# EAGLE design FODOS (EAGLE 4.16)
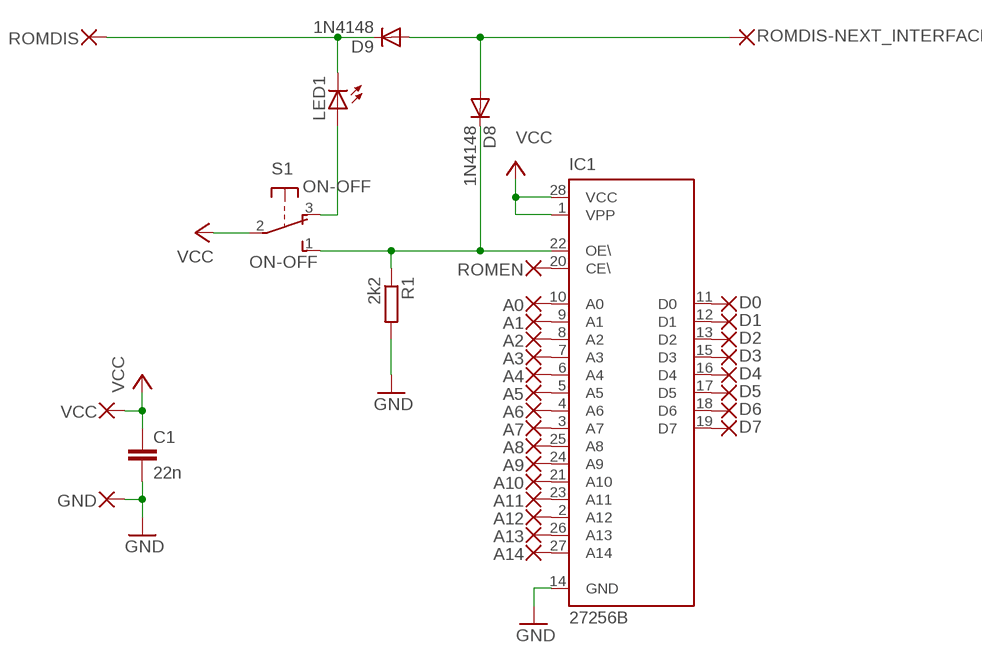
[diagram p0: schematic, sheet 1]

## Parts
A0  1,27-REDONDO1.0  [1,27/1,0-REDONDO]
A1  1,27-REDONDO1.0  [1,27/1,0-REDONDO]
A2  1,27-REDONDO1.0  [1,27/1,0-REDONDO]
A3  1,27-REDONDO1.0  [1,27/1,0-REDONDO]
A4  1,27-REDONDO1.0  [1,27/1,0-REDONDO]
A5  1,27-REDONDO1.0  [1,27/1,0-REDONDO]
A6  1,27-REDONDO1.0  [1,27/1,0-REDONDO]
A7  1,27-REDONDO1.0  [1,27/1,0-REDONDO]
A8  1,27-REDONDO1.0  [1,27/1,0-REDONDO]
A9  1,27-REDONDO1.0  [1,27/1,0-REDONDO]
A10  1,27-REDONDO1.0  [1,27/1,0-REDONDO]
A11  1,27-REDONDO1.0  [1,27/1,0-REDONDO]
A12  1,27-REDONDO1.0  [1,27/1,0-REDONDO]
A13  1,27-REDONDO1.0  [1,27/1,0-REDONDO]
A14  1,27-REDONDO1.0  [1,27/1,0-REDONDO]
C1  22n  C-EU050-024X044  [C050-024X044]
D0  1,27-REDONDO1.0  [1,27/1,0-REDONDO]
D1  1,27-REDONDO1.0  [1,27/1,0-REDONDO]
D2  1,27-REDONDO1.0  [1,27/1,0-REDONDO]
D3  1,27-REDONDO1.0  [1,27/1,0-REDONDO]
D4  1,27-REDONDO1.0  [1,27/1,0-REDONDO]
D5  1,27-REDONDO1.0  [1,27/1,0-REDONDO]
D6  1,27-REDONDO1.0  [1,27/1,0-REDONDO]
D7  1,27-REDONDO1.0  [1,27/1,0-REDONDO]
D8  1N4148  [DO35-10]
D9  1N4148  [DO35-10]
GND  1,27-REDONDO1.0  [1,27/1,0-REDONDO]
IC1  27256B  [DIL28-6B]
LED1  LED5MM  [LED5MM]
R1  2k2  R-EU_0207/7  [0207/7]
ROMDIS  1,27-REDONDO1.0  [1,27/1,0-REDONDO]
ROMDIS-NEXT_INTERFACE  1,27-REDONDO1.0  [1,27/1,0-REDONDO]
ROMEN  1,27-REDONDO1.0  [1,27/1,0-REDONDO]
S1  ON-OFF  9077-1  [9077-1]
VCC  1,27-REDONDO1.0  [1,27/1,0-REDONDO]

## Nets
A0: A0.P$1(P) IC1.10(A0)
A1: A1.P$1(P) IC1.9(A1)
A2: A2.P$1(P) IC1.8(A2)
A3: A3.P$1(P) IC1.7(A3)
A4: A4.P$1(P) IC1.6(A4)
A5: A5.P$1(P) IC1.5(A5)
A6: A6.P$1(P) IC1.4(A6)
A7: A7.P$1(P) IC1.3(A7)
A8: A8.P$1(P) IC1.25(A8)
A9: A9.P$1(P) IC1.24(A9)
A10: A10.P$1(P) IC1.21(A10)
A11: A11.P$1(P) IC1.23(A11)
A12: A12.P$1(P) IC1.2(A12)
A13: A13.P$1(P) IC1.26(A13)
A14: A14.P$1(P) IC1.27(A14)
D0: D0.P$1(P) IC1.11(D0)
D1: D1.P$1(P) IC1.12(D1)
D2: D2.P$1(P) IC1.13(D2)
D3: D3.P$1(P) IC1.15(D3)
D4: D4.P$1(P) IC1.16(D4)
D5: D5.P$1(P) IC1.17(D5)
D6: D6.P$1(P) IC1.18(D6)
D7: D7.P$1(P) IC1.19(D7)
GND: C1.2 GND.P$1(P) IC1.14(GND) R1.2
N$50: D8.A D9.A ROMDIS-NEXT_INTERFACE.P$1(P)
N$51: D8.C IC1.22(OE\) R1.1 S1.1(S)
N$52: LED1.A S1.3(O)
ROMDIS: D9.C LED1.K(C) ROMDIS.P$1(P)
ROMEN: IC1.20(CE\) ROMEN.P$1(P)
VCC: C1.1 IC1.1(VPP) IC1.28(VCC) S1.2(P) VCC.P$1(P)

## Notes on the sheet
- ON-OFF

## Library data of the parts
A0 A1-A14 D0 D1-D7 GND ROMDIS ROMDIS-NEXT_INTERFACE ROMEN VCC = wirepad2:1,27-REDONDO
C1 = rcl:C-EU: CAPACITOR, European symbol
D8 D9 = diode:1N4148: DIODE
IC1 = microchip:27*256: CMOS EPROM 256 K (32 K x 8), low voltage
LED1 = led:LED: LED
R1 = rcl:R-EU_: RESISTOR, European symbol
S1 = switch-misc:9077-1: MARQUARDT SWITCH

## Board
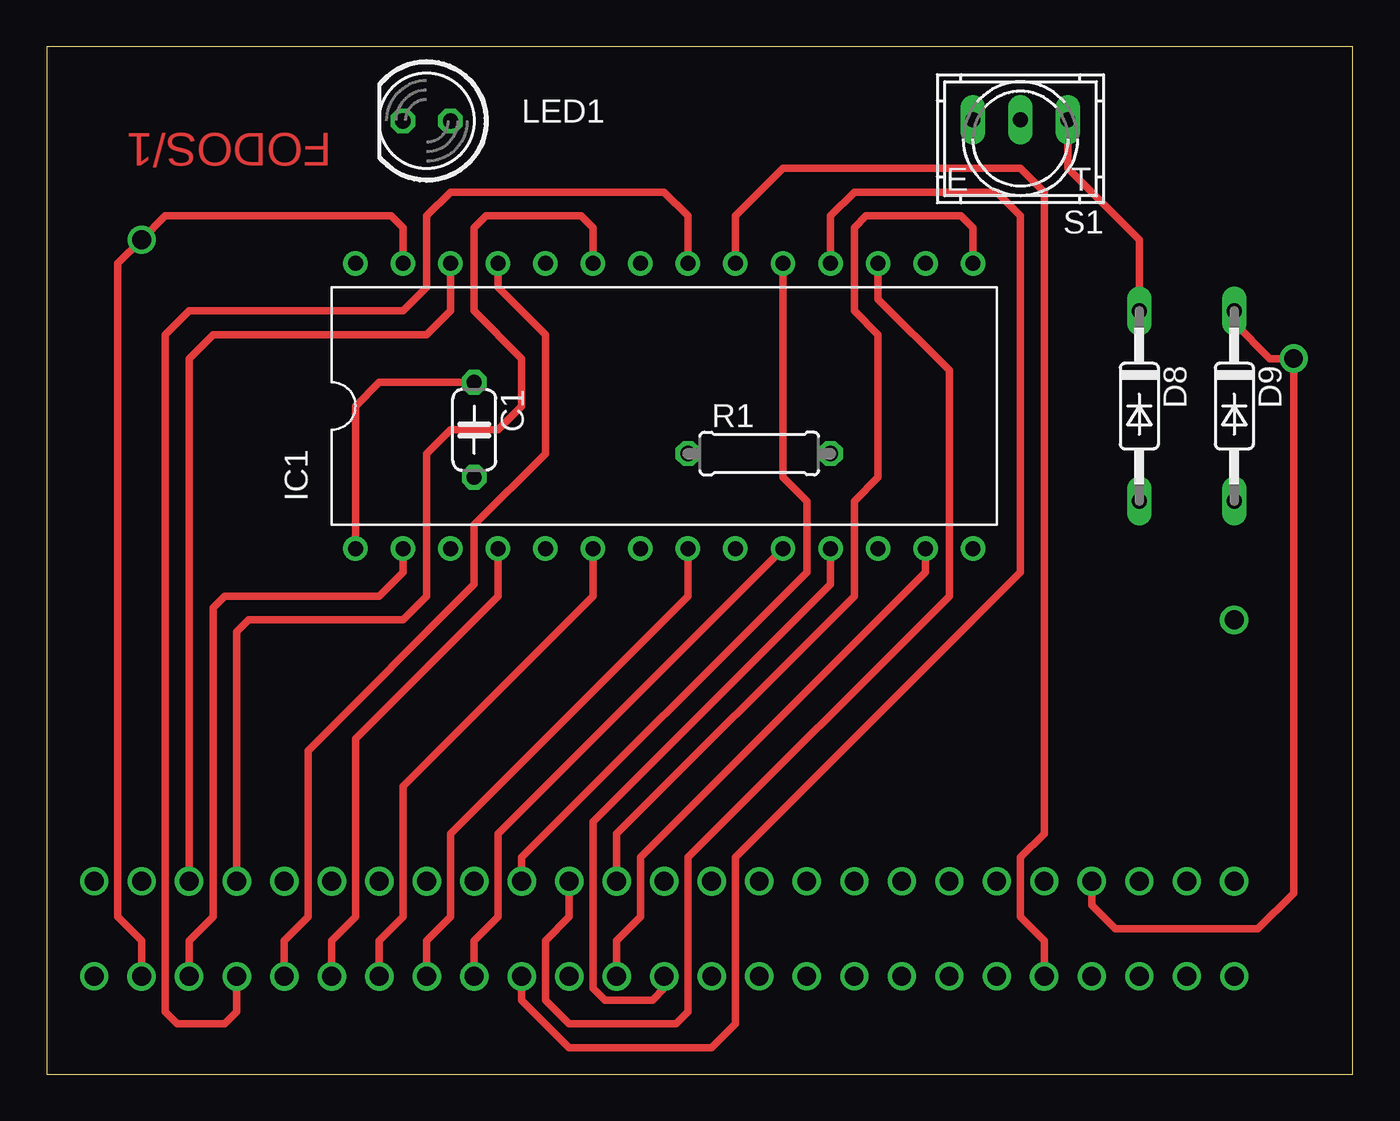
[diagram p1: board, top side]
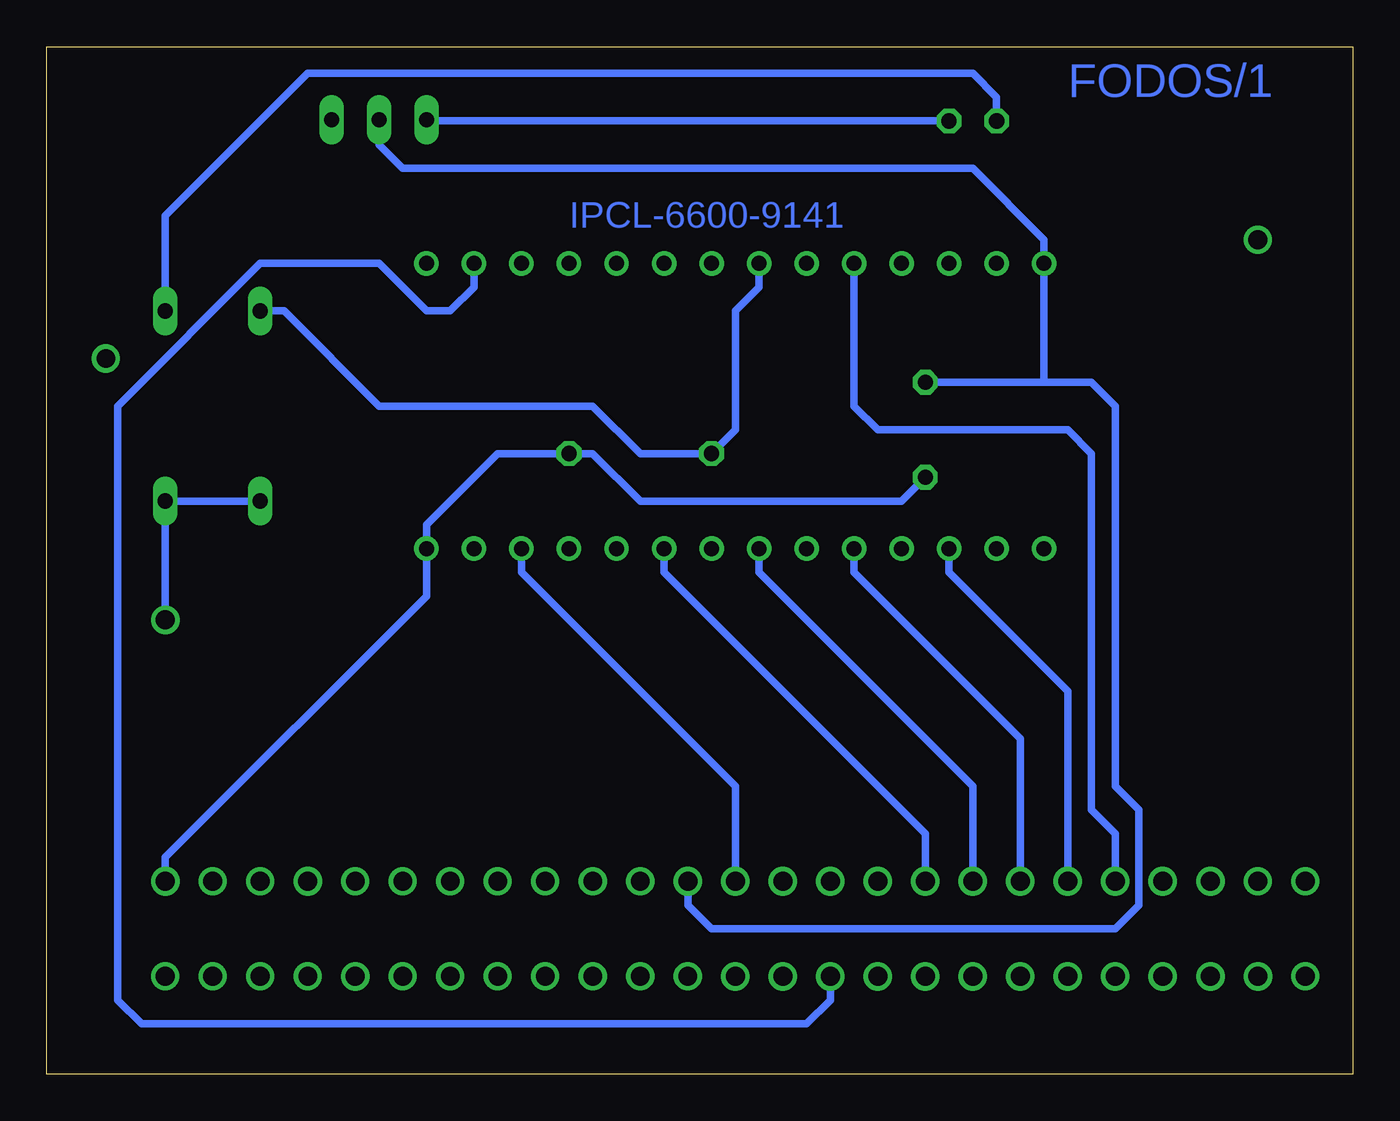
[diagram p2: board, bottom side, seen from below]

Size 69.83 x 54.92 mm. Coordinates in mm from the lower left corner, seen from the top.
Outline: 0,0 69.83,0 69.83,54.92 0,54.92 0,0
Copper layers (1*16): Top 0.035mm / dielectric 1.5mm / Bottom 0.035mm
Design rules "default": minimum track width 10mil, minimum drill 24mil, track to track 8mil, track to pad 8mil, pad to pad 8mil, via to via 8mil, smd to smd 8mil, copper to edge 40mil, drill to drill 8mil, minimum pad ring 10mil, minimum via ring 8mil, stop-mask expansion 4mil, vias tented up to drill 0mil, thermal gap 10mil

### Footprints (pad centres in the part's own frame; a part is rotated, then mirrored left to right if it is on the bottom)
1,27/1,0-REDONDO = drill 1.016 pad 1.422 round: P$1 0,0
C050-024X044 = drill 0.813 octagon: 1 -2.54,0; 2 2.54,0
DO35-10 = drill 0.813 long: A 5.08,0; C -5.08,0
DIL28-6B = drill 0.8 round: 1 -16.51,-7.62; 2 -13.97,-7.62; 3 -11.43,-7.62; 4 -8.89,-7.62; 5 -6.35,-7.62; 6 -3.81,-7.62; 7 -1.27,-7.62; 8 1.27,-7.62; 9 3.81,-7.62; 10 6.35,-7.62; 11 8.89,-7.62; 12 11.43,-7.62; 13 13.97,-7.62; 14 16.51,-7.62; 15 16.51,7.62; 16 13.97,7.62; 17 11.43,7.62; 18 8.89,7.62; 19 6.35,7.62; 20 3.81,7.62; 21 1.27,7.62; 22 -1.27,7.62; 23 -3.81,7.62; 24 -6.35,7.62; 25 -8.89,7.62; 26 -11.43,7.62; 27 -13.97,7.62; 28 -16.51,7.62
LED5MM = drill 0.813 octagon: A -1.27,0; K 1.27,0
0207/7 = drill 0.813 octagon: 1 -3.81,0; 2 3.81,0
9077-1 = drill 0.813 long: 1 -2.54,-1.016; 2 0,-1.016; 3 2.54,-1.016

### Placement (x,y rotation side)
A0  22.86,5.23 0 top
A1  22.86,10.31 0 top
A2  20.32,5.23 0 top
A3  20.32,10.31 0 top
A4  17.78,5.23 0 top
A5  17.78,10.31 0 top
A6  15.23,5.23 0 top
A7  15.23,10.31 0 top
A8  12.69,5.23 0 top
A9  12.69,10.31 0 top
A10  10.15,5.23 0 top
A11  10.15,10.31 0 top
A12  7.62,5.23 0 top
A13  7.62,10.31 0 top
A14  5.08,5.23 0 top
C1  22.86,34.44 270 top
D0  33.02,5.23 0 top
D1  33.02,10.31 0 top
D2  30.48,5.23 0 top
D3  30.48,10.31 0 top
D4  27.94,5.23 0 top
D5  27.94,10.31 0 top
D6  25.39,5.23 0 top
D7  25.39,10.31 0 top
D8  58.41,35.71 270 top
D9  63.49,35.71 270 top
GND  63.49,10.31 0 top
IC1  33.02,35.71 0 top
LED1  20.32,50.95 180 top
R1  38.09,33.17 0 top
ROMDIS  55.88,10.31 0 top
ROMDIS-NEXT_INTERFACE  63.49,24.28 90 top
ROMEN  53.34,5.23 0 top
S1  52.06,50 180 top
VCC  35.55,10.31 0 top

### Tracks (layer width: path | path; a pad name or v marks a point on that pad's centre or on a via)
A0
  Top 0.406: IC1.10 24.12,12.85 24.12,8.41 22.86,7.14 A0.P$1
A1
  Bottom 0.406: IC1.9 36.82,26.82 22.86,12.85 A1.P$1
A2
  Top 0.406: IC1.8 34.28,25.55 21.59,12.85 21.59,8.41 20.32,7.14 A2.P$1
A3
  Bottom 0.406: IC1.7 31.75,26.82 20.32,15.39 A3.P$1
A4
  Top 0.406: IC1.6 29.21,25.55 19.05,15.39 19.05,8.41 17.78,7.14 A4.P$1
A5
  Bottom 0.406: IC1.5 26.67,26.82 17.78,17.93 A5.P$1
A6
  Top 0.406: IC1.4 24.12,25.55 16.51,17.93 16.51,8.41 15.23,7.14 A6.P$1
A7
  Bottom 0.406: IC1.3 21.59,26.82 15.23,20.47 A7.P$1
A8
  Top 0.406: A8.P$1 12.69,7.14 13.96,8.41 13.96,17.3 22.86,26.19 22.86,29.36 26.67,33.17 26.67,39.52 24.12,42.06 IC1.25
A9
  Bottom 0.406: A9.P$1 12.69,12.85 13.96,14.12 13.96,33.17 15.23,34.44 25.39,34.44 26.67,35.71 IC1.24
A10
  Top 0.406: A10.P$1 10.15,3.33 9.52,2.69 6.98,2.69 6.34,3.33 6.34,39.52 7.62,40.79 19.05,40.79 20.32,42.06 20.32,45.87 21.59,47.14 33.02,47.14 34.28,45.87 IC1.21
A11
  Top 0.406: A11.P$1 10.15,23.65 10.79,24.28 19.05,24.28 20.32,25.55 20.32,33.17 21.59,34.44 24.12,34.44 25.39,35.71 25.39,38.25 22.86,40.79 22.86,45.24 23.49,45.87 28.57,45.87 29.21,45.24 IC1.23
A12
  Top 0.406: IC1.2 19.05,26.82 17.78,25.55 9.52,25.55 8.88,24.92 8.88,8.41 7.62,7.14 A12.P$1
A13
  Top 0.406: A13.P$1 7.62,38.25 8.88,39.52 20.32,39.52 21.59,40.79 IC1.26
A14  (via drill 1)
  Top 0.406: A14.P$1 5.08,7.14 3.81,8.41 3.81,43.33 v5.08,44.6 6.34,45.87 18.41,45.87 19.05,45.24 IC1.27
D0
  Top 0.406: D0.P$1 33.02,4.6 32.38,3.96 29.84,3.96 29.21,4.6 29.21,13.49 41.9,26.19 IC1.11
D1
  Bottom 0.406: IC1.12 44.45,26.82 33.02,15.39 D1.P$1
D2
  Top 0.406: D2.P$1 30.48,7.14 31.75,8.41 31.75,11.58 46.98,26.82 IC1.13
D3
  Top 0.406: IC1.15 49.52,45.24 48.89,45.87 43.81,45.87 43.17,45.24 43.17,40.79 44.45,39.52 44.45,31.9 43.17,30.63 43.17,25.55 30.48,12.85 D3.P$1
D4
  Bottom 0.406: IC1.16 46.98,42.06 48.25,40.79 49.52,40.79 52.06,43.33 58.41,43.33 66.04,35.71 66.04,3.96 64.77,2.69 29.21,2.69 27.94,3.96 D4.P$1
D5
  Top 0.406: D5.P$1 27.94,8.41 26.67,7.14 26.67,3.96 27.94,2.69 33.65,2.69 34.28,3.33 34.28,11.58 48.25,25.55 48.25,37.62 44.45,41.43 IC1.17
D6
  Top 0.406: IC1.18 41.9,45.87 43.17,47.14 50.79,47.14 52.06,45.87 52.06,26.82 36.82,11.58 36.82,2.69 35.55,1.42 27.94,1.42 25.39,3.96 D6.P$1
D7
  Top 0.406: IC1.19 39.36,31.9 40.63,30.63 40.63,26.82 25.39,11.58 D7.P$1
GND
  Bottom 0.406: GND.P$1 63.49,11.58 49.52,25.55 IC1.14 49.52,29.36 45.71,33.17 R1.2 40.63,33.17 38.09,30.63 24.12,30.63 C1.2
N$24  (via drill 1)
  other vias: 2.54,5.23
N$25  (via drill 1)
  other vias: 5.08,10.31
N$26  (via drill 1)
  other vias: 2.54,10.31
N$27  (via drill 1)
  other vias: 38.09,10.31
N$28  (via drill 1)
  other vias: 40.63,10.31
N$29  (via drill 1)
  other vias: 43.17,10.31
N$30  (via drill 1)
  other vias: 45.71,10.31
N$31  (via drill 1)
  other vias: 48.25,10.31
N$32  (via drill 1)
  other vias: 50.79,10.31
N$33  (via drill 1)
  other vias: 53.34,10.31
N$34  (via drill 1)
  other vias: 66.67,38.25
N$35  (via drill 1)
  other vias: 58.41,10.31
N$36  (via drill 1)
  other vias: 60.95,10.31
N$37  (via drill 1)
  other vias: 60.95,5.23
N$38  (via drill 1)
  other vias: 58.41,5.23
N$39  (via drill 1)
  other vias: 55.88,5.23
N$41  (via drill 1)
  other vias: 50.79,5.23
N$42  (via drill 1)
  other vias: 48.25,5.23
N$43  (via drill 1)
  other vias: 45.71,5.23
N$44  (via drill 1)
  other vias: 43.17,5.23
N$45  (via drill 1)
  other vias: 40.63,5.23
N$46  (via drill 1)
  other vias: 38.09,5.23
N$47  (via drill 1)
  other vias: 35.55,5.23
N$48  (via drill 1)
  other vias: 63.49,5.23
N$50
  Bottom 0.406: D8.A D9.A ROMDIS-NEXT_INTERFACE.P$1
N$51
  Top 0.406: D8.C 58.41,44.6 54.6,48.41 S1.1
  Bottom 0.406: IC1.22 31.75,42.06 33.02,40.79 33.02,34.44 R1.1 38.09,33.17 40.63,35.71 52.06,35.71 57.14,40.79 D8.C
N$52
  Bottom 0.406: S1.3 49.52,50.95 LED1.A
ROMDIS
  Top 0.406: ROMDIS.P$1 55.88,9.04 57.14,7.77 64.77,7.77 66.67,9.68 66.67,38.25 65.4,38.25 63.49,40.16 D9.C
  Bottom 0.406: LED1.K 19.05,52.22 20.32,53.49 55.88,53.49 63.49,45.87 D9.C
ROMEN
  Top 0.406: ROMEN.P$1 53.34,7.14 52.06,8.41 52.06,11.58 53.34,12.85 53.34,47.14 52.06,48.41 39.36,48.41 36.82,45.87 IC1.20
VCC
  Top 0.406: IC1.1 16.51,35.71 17.78,36.98 C1.1
  Bottom 0.406: VCC.P$1 35.55,9.04 34.28,7.77 12.69,7.77 11.42,9.04 11.42,14.12 12.69,15.39 12.69,35.71 13.96,36.98 16.51,36.98 | 16.51,36.98 IC1.28 16.51,44.6 20.32,48.41 50.79,48.41 52.06,49.68 S1.2 | 16.51,36.98 C1.1

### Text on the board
Top: FODOS/1
Bottom: FODOS/1 | IPCL-6600-9141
